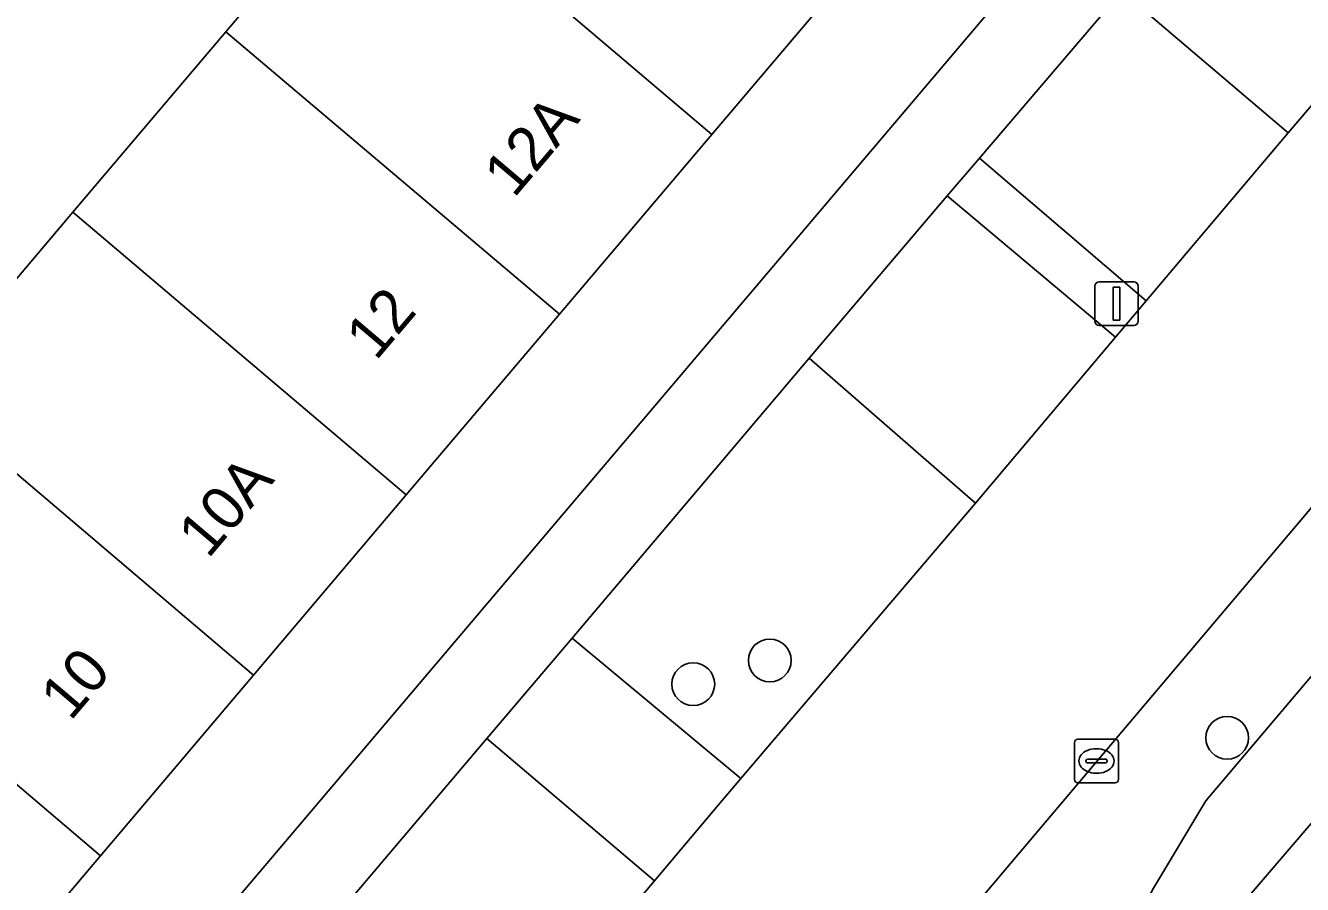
# Model space of a CAD drawing. Extents: x 156412 to 157779, y 382335 to 383768.
# Drawn here: x 156807.67 to 156836.83, y 382524 to 382543.62 of the extents above; entities that cross this region are included whole.
import ezdxf

# ---------------------------------------------------------------- set-up
doc = ezdxf.new("R2010")
doc.units = 0
for name, color, linetype in [('IMGEO_Berm_groen', 7, 'Continuous'), ('IMGEO_Boom', 7, 'Continuous'), ('IMGEO_Erf', 7, 'Continuous'), ('IMGEO_Groenvoorziening', 7, 'Continuous'), ('IMGEO_Kolk', 7, 'Continuous'), ('IMGEO_Lichtmast', 7, 'Continuous'), ('IMGEO_Oever', 7, 'Continuous'), ('IMGEO_Pand', 7, 'Continuous'), ('IMGEO_Pand_nummerreeks', 7, 'Continuous'), ('IMGEO_Parkeervlak_open', 7, 'Continuous'), ('IMGEO_Rijbaan_lokaal_gesloten', 7, 'Continuous'), ('IMGEO_Voetpad_open', 7, 'Continuous'), ('IMGEO_Waterloop', 7, 'Continuous')]:
    doc.layers.add(name, color=color, linetype=linetype)

msp = doc.modelspace()

# ---------------------------------------------------------------- linework, layer by layer
at = {"layer": 'IMGEO_Berm_groen'}
for points in [[(156840.532, 382545.9), (156836.723, 382549.204), (156832.703, 382544.406), (156836.503, 382541.171)], [(156829.365, 382532.712), (156825.562, 382536.018), (156820.151, 382529.626), (156824.005, 382526.416)]]:
    msp.add_lwpolyline(points, close=True, dxfattribs=at)
at = {"layer": 'IMGEO_Boom'}
for centre in [(156824.666, 382529.116), (156822.918, 382528.574), (156835.112, 382527.349)]:
    msp.add_circle(centre, 0.489, dxfattribs=at)
at = {"layer": 'IMGEO_Erf'}
for points in [[(156784.875, 382491.099), (156856.496, 382575.585), (156855.848, 382576.066)], [(156812.239, 382543.473), (156815.727, 382547.596)], [(156826.844, 382545.267), (156823.342, 382541.134), (156819.86, 382537.024), (156816.364, 382532.897), (156812.875, 382528.779), (156809.38, 382524.653), (156805.896, 382520.541), (156802.395, 382516.408), (156798.906, 382512.289), (156795.408, 382508.191), (156791.934, 382504.06), (156788.454, 382499.952), (156781.958, 382492.284), (156779.822, 382494.101)], [(156780.814, 382506.406), (156784.311, 382510.531), (156787.804, 382514.649), (156791.294, 382518.766), (156794.784, 382522.882), (156798.278, 382527.002), (156801.774, 382531.125), (156805.269, 382535.247), (156808.751, 382539.353), (156812.239, 382543.473)]]:
    msp.add_lwpolyline(points, dxfattribs=at)
at = {"layer": 'IMGEO_Groenvoorziening'}
msp.add_lwpolyline([(156833.429, 382523.914), (156834.624, 382525.907), (156865.157, 382561.969), (156883.467, 382582.632), (156881.147, 382584.59), (156855.391, 382554.226), (156843.769, 382540.567), (156831.328, 382525.852), (156828.33, 382522.305), (156828.27, 382522.229), (156828.21, 382522.153), (156838.048, 382513.792), (156840.059, 382516.222), (156839.658, 382516.575), (156839.538, 382516.434), (156839.257, 382516.694), (156890.335, 382576.835), (156888.158, 382578.673), (156866.603, 382552.72), (156839.563, 382521.34), (156836.701, 382518.344)], dxfattribs=at)
at = {"layer": 'IMGEO_Kolk'}
for p, q in [((156831.702, 382527.319), (156832.554, 382527.319)), ((156831.627, 382526.393), (156831.627, 382527.245)), ((156832.115, 382527.099), (156832.14, 382527.099)), ((156832.628, 382527.245), (156832.628, 382526.393)), ((156831.886, 382526.813), (156831.886, 382526.825)), ((156832.324, 382526.776), (156831.926, 382526.776)), ((156831.929, 382526.862), (156832.327, 382526.862)), ((156832.37, 382526.825), (156832.37, 382526.813)), ((156832.138, 382526.539), (156832.113, 382526.539)), ((156832.554, 382526.319), (156831.702, 382526.319))]:
    msp.add_line(p, q, dxfattribs=at)
for points in [[(156831.702, 382527.319), (156832.554, 382527.319)], [(156831.627, 382526.393), (156831.627, 382527.245)], [(156832.628, 382527.245), (156832.628, 382526.393)], [(156832.554, 382526.319), (156831.702, 382526.319)]]:
    msp.add_lwpolyline(points, dxfattribs=at)
for centre, radius, start, end in [((156831.704, 382527.243), 0.0765, 91.552, 178.448), ((156831.704, 382527.243), 0.0765, 91.552, 178.448), ((156832.552, 382527.243), 0.0765, 1.552, 88.448), ((156832.552, 382527.243), 0.0765, 1.552, 88.448), ((156831.926, 382526.822), 0.0403, 85.8775, 175.7526), ((156831.923, 382526.812), 0.0366, 178.938, 274.7102), ((156832.327, 382526.819), 0.043, 264.8664, 352.4533), ((156832.331, 382526.824), 0.0386, 1.7309, 96.639), ((156831.704, 382526.395), 0.0765, 181.552, 268.448), ((156831.704, 382526.395), 0.0765, 181.552, 268.448), ((156832.552, 382526.395), 0.0765, 271.552, 358.448), ((156832.552, 382526.395), 0.0765, 271.552, 358.448)]:
    msp.add_arc(centre, radius, start, end, dxfattribs=at)
for centre, major_axis, ratio, start_param, end_param in [((156832.114, 382526.819), (-0.387, 0.002), 0.722429, 4.712389, 7.853982), ((156832.139, 382526.819), (-0.39, 0.002), 0.717154, 1.570796, 4.712389)]:
    msp.add_ellipse(centre, major_axis=major_axis, ratio=ratio, start_param=start_param, end_param=end_param, dxfattribs=at)
at = {"layer": 'IMGEO_Lichtmast'}
for p, q in [((156832.189, 382537.767), (156832.979, 382537.767)), ((156832.979, 382537.767), (156832.189, 382537.767)), ((156832.089, 382536.867), (156832.089, 382537.667)), ((156832.089, 382537.667), (156832.089, 382536.867)), ((156833.079, 382537.667), (156833.079, 382536.867)), ((156833.079, 382536.867), (156833.079, 382537.667)), ((156832.979, 382536.767), (156832.189, 382536.767)), ((156832.189, 382536.767), (156832.979, 382536.767))]:
    msp.add_line(p, q, dxfattribs=at)
msp.add_lwpolyline([(156832.509, 382537.642), (156832.659, 382537.642), (156832.659, 382536.892), (156832.509, 382536.892), (156832.509, 382537.642)], dxfattribs=at)
for centre, start, end in [((156832.189, 382537.667), 90, 180), ((156832.189, 382537.667), 90, 180), ((156832.979, 382537.667), 0, 90), ((156832.979, 382537.667), 360, 90), ((156832.189, 382536.867), 180, 270), ((156832.189, 382536.867), 180, 270), ((156832.979, 382536.867), 270, 0), ((156832.979, 382536.867), 270, 0)]:
    msp.add_arc(centre, 0.1, start, end, dxfattribs=at)
at = {"layer": 'IMGEO_Oever'}
msp.add_lwpolyline([(156883.467, 382582.632), (156865.157, 382561.969), (156834.624, 382525.907), (156833.429, 382523.914), (156832.515, 382522.224)], dxfattribs=at)
msp.add_lwpolyline([(156885.526, 382578.584), (156845.993, 382531.875), (156836.354, 382521.047), (156834.528, 382522.47), (156883.743, 382579.943)], close=True, dxfattribs=at)
at = {"layer": 'IMGEO_Pand'}
for points in [[(156826.844, 382545.267), (156819.221, 382551.725), (156815.727, 382547.596), (156823.342, 382541.134)], [(156815.727, 382547.596), (156812.239, 382543.473), (156819.86, 382537.024), (156823.342, 382541.134)], [(156808.751, 382539.353), (156816.364, 382532.897), (156819.86, 382537.024), (156812.239, 382543.473)], [(156808.751, 382539.353), (156805.269, 382535.247), (156812.875, 382528.779), (156816.364, 382532.897)], [(156812.875, 382528.779), (156805.269, 382535.247), (156801.774, 382531.125), (156809.38, 382524.653)], [(156798.278, 382527.002), (156805.896, 382520.541), (156809.38, 382524.653), (156801.774, 382531.125)]]:
    msp.add_lwpolyline(points, close=True, dxfattribs=at)
at = {"layer": 'IMGEO_Parkeervlak_open'}
for points in [[(156836.503, 382541.171), (156832.703, 382544.406), (156829.453, 382540.589), (156833.261, 382537.329)], [(156832.562, 382536.501), (156828.72, 382539.728), (156825.562, 382536.018), (156829.365, 382532.712)], [(156822.03, 382524.083), (156818.205, 382527.33), (156813.377, 382521.637), (156817.149, 382518.304)]]:
    msp.add_lwpolyline(points, close=True, dxfattribs=at)
at = {"layer": 'IMGEO_Rijbaan_lokaal_gesloten'}
for points in [[(156840.532, 382545.9), (156836.503, 382541.171), (156833.261, 382537.329), (156832.562, 382536.501), (156829.365, 382532.712), (156824.005, 382526.416), (156823.493, 382525.815), (156822.03, 382524.083), (156817.149, 382518.304), (156812.057, 382512.315), (156807.197, 382506.592), (156806.531, 382505.808), (156804.886, 382503.871), (156800.842, 382499.119), (156796.053, 382493.441), (156792.11, 382488.95)], [(156828.21, 382522.153), (156828.27, 382522.229), (156828.33, 382522.305), (156831.328, 382525.852), (156843.769, 382540.567)]]:
    msp.add_lwpolyline(points, dxfattribs=at)
at = {"layer": 'IMGEO_Voetpad_open'}
for points in [[(156858.275, 382574.531), (156859.329, 382575.743), (156857.81, 382577.079), (156856.496, 382575.585), (156784.875, 382491.099)], [(156825.562, 382536.018), (156828.72, 382539.728), (156829.453, 382540.589), (156832.703, 382544.406), (156836.723, 382549.204), (156841.535, 382554.878), (156842.26, 382555.733), (156843.897, 382557.663), (156848.622, 382563.205), (156853.438, 382568.866), (156854.147, 382569.699), (156855.833, 382571.681), (156859.65, 382568.411), (156860.138, 382569.338), (156860.522, 382570.35), (156858.613, 382571.978)], [(156792.11, 382488.95), (156788.319, 382492.08), (156792.25, 382496.725), (156797.041, 382502.382), (156801.08, 382507.085), (156802.717, 382509.026), (156803.379, 382509.811), (156808.214, 382515.542), (156813.377, 382521.637), (156818.205, 382527.33), (156819.635, 382529.016), (156820.151, 382529.626), (156825.562, 382536.018)]]:
    msp.add_lwpolyline(points, dxfattribs=at)
for points in [[(156829.453, 382540.589), (156828.72, 382539.728), (156832.562, 382536.501), (156833.261, 382537.329)], [(156820.151, 382529.626), (156819.635, 382529.016), (156818.205, 382527.33), (156822.03, 382524.083), (156823.493, 382525.815), (156824.005, 382526.416)]]:
    msp.add_lwpolyline(points, close=True, dxfattribs=at)
at = {"layer": 'IMGEO_Waterloop'}
msp.add_lwpolyline([(156834.528, 382522.47), (156836.354, 382521.047), (156845.993, 382531.875), (156885.526, 382578.584), (156883.743, 382579.943)], close=True, dxfattribs=at)

# ---------------------------------------------------------------- texts
at = {"layer": 'IMGEO_Pand_nummerreeks'}
for s, rotation, p in [('12A', 49.7163, (156818.823, 382539.659)), ('12', 49.7126, (156815.671, 382535.942)), ('10A', 49.7094, (156811.839, 382531.421)), ('10', 49.7126, (156808.694, 382527.711))]:
    msp.add_text(s, height=1, rotation=rotation, dxfattribs=at).set_placement(p)

doc.saveas('drawing.dxf')
